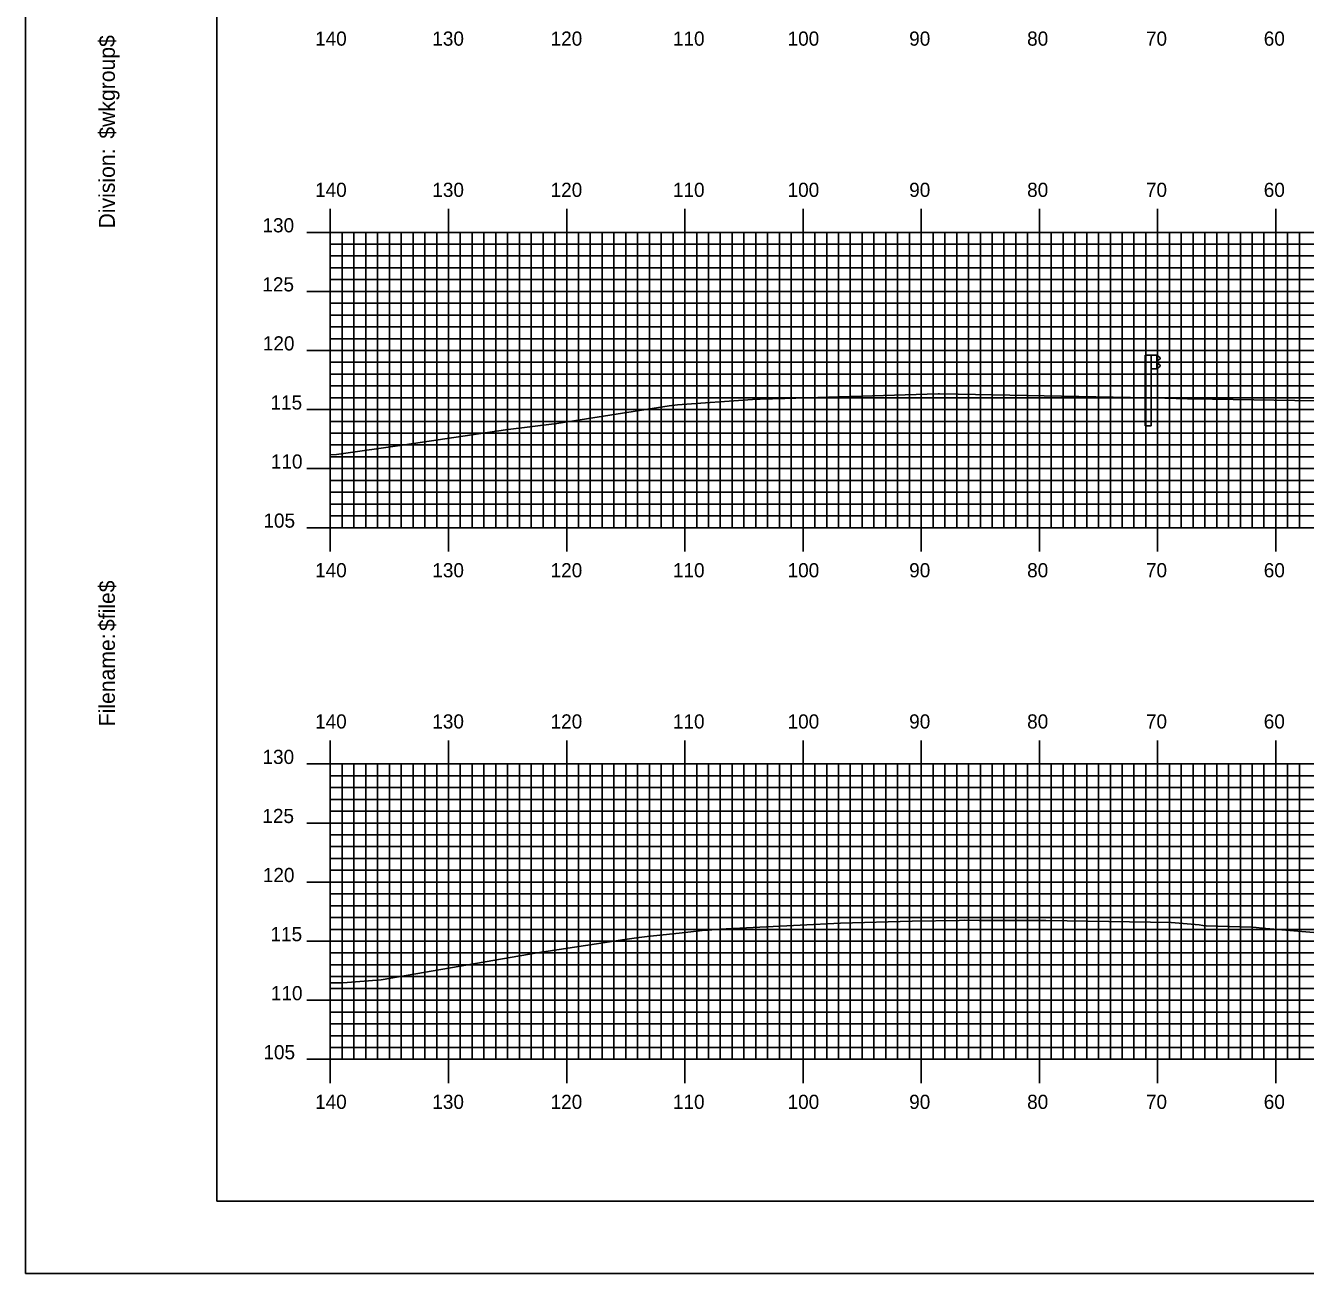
# Model space of a CAD drawing. Extents: x 1754314 to 1754654, y 442591 to 442811.
# Drawn here: x 1754314.2 to 1754422.5, y 442590.5 to 442696.2 of the extents above; entities that cross this region are included whole.
import ezdxf

# ---------------------------------------------------------------- set-up
doc = ezdxf.new("R2010")
doc.units = 0
for name, color, linetype in [('BORDER', 7, 'Continuous'), ('H_V ANNOTATION', 7, 'Continuous'), ('M_Guardrail', 7, 'Continuous'), ('M_Roadway_Centerline', 7, 'Continuous'), ('MAJOR', 7, 'Continuous'), ('MINOR', 7, 'Continuous'), ('PLOT BOUNDARY', 7, 'Continuous'), ('S_Roadway_Centerline', 7, 'Continuous')]:
    doc.layers.add(name, color=color, linetype=linetype)

msp = doc.modelspace()

# ---------------------------------------------------------------- linework, layer by layer
at = {"layer": 'BORDER'}
msp.add_lwpolyline([(1754330.4, 442596.67), (1754650.4, 442596.67), (1754650.4, 442806.67), (1754330.4, 442806.67)], close=True, dxfattribs=at)
at = {"layer": 'M_Guardrail'}
for p, q in [((1754408.96, 442668.28), (1754408.96, 442662.28)), ((1754409.45, 442668.28), (1754408.96, 442668.28)), ((1754409.94, 442668.28), (1754409.45, 442668.28)), ((1754409.45, 442668.28), (1754409.45, 442667.11)), ((1754409.94, 442667.11), (1754409.94, 442668.28)), ((1754409.94, 442668.21), (1754410.02, 442668.19)), ((1754409.95, 442667.74), (1754409.95, 442667.65)), ((1754410.18, 442667.94), (1754409.99, 442667.81)), ((1754409.99, 442667.59), (1754410.18, 442667.45)), ((1754410.04, 442668.19), (1754410.18, 442668.09)), ((1754409.45, 442662.28), (1754409.45, 442667.11)), ((1754409.45, 442667.11), (1754409.94, 442667.11)), ((1754410.02, 442667.2), (1754409.94, 442667.19)), ((1754410.18, 442667.31), (1754410.04, 442667.21)), ((1754409.45, 442662.28), (1754408.96, 442662.28))]:
    msp.add_line(p, q, dxfattribs=at)
for centre, major_axis, start_param, end_param in [((1754410.03, 442667.74), (-0.0789, 0), 5.323254, 6.283185), ((1754410.03, 442667.65), (-0.0789, 0), 6.283185, 7.243116), ((1754410.01, 442668.15), (0.0417, 0), 0.959931, 1.396263), ((1754410.13, 442668.01), (0.0877, 0), 5.323254, 7.243116), ((1754410.13, 442667.38), (0.0877, 0), 5.323254, 7.243116), ((1754410.01, 442667.24), (0.0417, 0), 4.886922, 5.323254)]:
    msp.add_ellipse(centre, major_axis=major_axis, ratio=0.995501, start_param=start_param, end_param=end_param, dxfattribs=at)
at = {"layer": 'MAJOR'}
for p, q in [((1754340, 442680.67), (1754340, 442678.67)), ((1754350, 442680.67), (1754350, 442678.67)), ((1754360, 442680.67), (1754360, 442678.67)), ((1754370, 442680.67), (1754370, 442678.67)), ((1754380, 442680.67), (1754380, 442678.67)), ((1754390, 442680.67), (1754390, 442678.67)), ((1754400, 442680.67), (1754400, 442678.67)), ((1754410, 442680.67), (1754410, 442678.67)), ((1754420, 442680.67), (1754420, 442678.67)), ((1754338, 442678.67), (1754340, 442678.67)), ((1754340, 442678.67), (1754620, 442678.67)), ((1754340, 442653.67), (1754340, 442678.67)), ((1754340, 442653.67), (1754340, 442678.67)), ((1754340, 442678.67), (1754620, 442678.67)), ((1754350, 442653.67), (1754350, 442678.67)), ((1754360, 442653.67), (1754360, 442678.67)), ((1754370, 442653.67), (1754370, 442678.67)), ((1754380, 442653.67), (1754380, 442678.67)), ((1754390, 442653.67), (1754390, 442678.67)), ((1754400, 442653.67), (1754400, 442678.67)), ((1754410, 442653.67), (1754410, 442678.67)), ((1754420, 442653.67), (1754420, 442678.67)), ((1754338, 442673.67), (1754340, 442673.67)), ((1754338, 442668.67), (1754340, 442668.67)), ((1754340, 442668.67), (1754620, 442668.67)), ((1754338, 442663.67), (1754340, 442663.67)), ((1754340, 442663.67), (1754620, 442663.67)), ((1754338, 442658.67), (1754340, 442658.67)), ((1754340, 442658.67), (1754620, 442658.67)), ((1754338, 442653.67), (1754340, 442653.67)), ((1754340, 442653.67), (1754620, 442653.67)), ((1754340, 442653.67), (1754620, 442653.67)), ((1754340, 442651.66), (1754340, 442653.67)), ((1754350, 442651.66), (1754350, 442653.67)), ((1754360, 442651.66), (1754360, 442653.67)), ((1754370, 442651.66), (1754370, 442653.67)), ((1754380, 442651.66), (1754380, 442653.67)), ((1754390, 442651.66), (1754390, 442653.67)), ((1754400, 442651.66), (1754400, 442653.67)), ((1754410, 442651.66), (1754410, 442653.67)), ((1754420, 442651.66), (1754420, 442653.67)), ((1754340, 442635.67), (1754340, 442633.67)), ((1754350, 442635.67), (1754350, 442633.67)), ((1754360, 442635.67), (1754360, 442633.67)), ((1754370, 442635.67), (1754370, 442633.67)), ((1754380, 442635.67), (1754380, 442633.67)), ((1754390, 442635.67), (1754390, 442633.67)), ((1754400, 442635.67), (1754400, 442633.67)), ((1754410, 442635.67), (1754410, 442633.67)), ((1754420, 442635.67), (1754420, 442633.67)), ((1754338, 442633.67), (1754340, 442633.67)), ((1754340, 442633.67), (1754620, 442633.67)), ((1754340, 442608.67), (1754340, 442633.67)), ((1754340, 442608.67), (1754340, 442633.67)), ((1754340, 442633.67), (1754620, 442633.67)), ((1754350, 442608.67), (1754350, 442633.67)), ((1754360, 442608.67), (1754360, 442633.67)), ((1754370, 442608.67), (1754370, 442633.67)), ((1754380, 442608.67), (1754380, 442633.67)), ((1754390, 442608.67), (1754390, 442633.67)), ((1754400, 442608.67), (1754400, 442633.67)), ((1754410, 442608.67), (1754410, 442633.67)), ((1754420, 442608.67), (1754420, 442633.67)), ((1754338, 442628.67), (1754340, 442628.67)), ((1754340, 442628.67), (1754620, 442628.67)), ((1754338, 442623.67), (1754340, 442623.67)), ((1754340, 442623.67), (1754620, 442623.67)), ((1754338, 442618.67), (1754340, 442618.67)), ((1754340, 442618.67), (1754620, 442618.67)), ((1754338, 442613.67), (1754340, 442613.67)), ((1754340, 442613.67), (1754620, 442613.67)), ((1754338, 442608.67), (1754340, 442608.67)), ((1754340, 442608.67), (1754620, 442608.67)), ((1754340, 442608.67), (1754620, 442608.67)), ((1754340, 442606.66), (1754340, 442608.67)), ((1754350, 442606.66), (1754350, 442608.67)), ((1754360, 442606.66), (1754360, 442608.67)), ((1754370, 442606.66), (1754370, 442608.67)), ((1754380, 442606.66), (1754380, 442608.67)), ((1754390, 442606.66), (1754390, 442608.67)), ((1754400, 442606.66), (1754400, 442608.67)), ((1754410, 442606.66), (1754410, 442608.67)), ((1754420, 442606.66), (1754420, 442608.67))]:
    msp.add_line(p, q, dxfattribs=at)
at = {"layer": 'MINOR'}
for p, q in [((1754341, 442653.67), (1754341, 442678.67)), ((1754342, 442653.67), (1754342, 442678.67)), ((1754343, 442653.67), (1754343, 442678.67)), ((1754344, 442653.67), (1754344, 442678.67)), ((1754345, 442653.67), (1754345, 442678.67)), ((1754346, 442653.67), (1754346, 442678.67)), ((1754347, 442653.67), (1754347, 442678.67)), ((1754348, 442653.67), (1754348, 442678.67)), ((1754349, 442653.67), (1754349, 442678.67)), ((1754351, 442653.67), (1754351, 442678.67)), ((1754352, 442653.67), (1754352, 442678.67)), ((1754353, 442653.67), (1754353, 442678.67)), ((1754354, 442653.67), (1754354, 442678.67)), ((1754355, 442653.67), (1754355, 442678.67)), ((1754356, 442653.67), (1754356, 442678.67)), ((1754357, 442653.67), (1754357, 442678.67)), ((1754358, 442653.67), (1754358, 442678.67)), ((1754359, 442653.67), (1754359, 442678.67)), ((1754361, 442653.67), (1754361, 442678.67)), ((1754362, 442653.67), (1754362, 442678.67)), ((1754363, 442653.67), (1754363, 442678.67)), ((1754364, 442653.67), (1754364, 442678.67)), ((1754365, 442653.67), (1754365, 442678.67)), ((1754366, 442653.67), (1754366, 442678.67)), ((1754367, 442653.67), (1754367, 442678.67)), ((1754368, 442653.67), (1754368, 442678.67)), ((1754369, 442653.67), (1754369, 442678.67)), ((1754371, 442653.67), (1754371, 442678.67)), ((1754372, 442653.67), (1754372, 442678.67)), ((1754373, 442653.67), (1754373, 442678.67)), ((1754374, 442653.67), (1754374, 442678.67)), ((1754375, 442653.67), (1754375, 442678.67)), ((1754376, 442653.67), (1754376, 442678.67)), ((1754377, 442653.67), (1754377, 442678.67)), ((1754378, 442653.67), (1754378, 442678.67)), ((1754379, 442653.67), (1754379, 442678.67)), ((1754381, 442653.67), (1754381, 442678.67)), ((1754382, 442653.67), (1754382, 442678.67)), ((1754383, 442653.67), (1754383, 442678.67)), ((1754384, 442653.67), (1754384, 442678.67)), ((1754385, 442653.67), (1754385, 442678.67)), ((1754386, 442653.67), (1754386, 442678.67)), ((1754387, 442653.67), (1754387, 442678.67)), ((1754388, 442653.67), (1754388, 442678.67)), ((1754389, 442653.67), (1754389, 442678.67)), ((1754391, 442653.67), (1754391, 442678.67)), ((1754392, 442653.67), (1754392, 442678.67)), ((1754393, 442653.67), (1754393, 442678.67)), ((1754394, 442653.67), (1754394, 442678.67)), ((1754395, 442653.67), (1754395, 442678.67)), ((1754396, 442653.67), (1754396, 442678.67)), ((1754397, 442653.67), (1754397, 442678.67)), ((1754398, 442653.67), (1754398, 442678.67)), ((1754399, 442653.67), (1754399, 442678.67)), ((1754401, 442653.67), (1754401, 442678.67)), ((1754402, 442653.67), (1754402, 442678.67)), ((1754403, 442653.67), (1754403, 442678.67)), ((1754404, 442653.67), (1754404, 442678.67)), ((1754405, 442653.67), (1754405, 442678.67)), ((1754406, 442653.67), (1754406, 442678.67)), ((1754407, 442653.67), (1754407, 442678.67)), ((1754408, 442653.67), (1754408, 442678.67)), ((1754409, 442653.67), (1754409, 442678.67)), ((1754411, 442653.67), (1754411, 442678.67)), ((1754412, 442653.67), (1754412, 442678.67)), ((1754413, 442653.67), (1754413, 442678.67)), ((1754414, 442653.67), (1754414, 442678.67)), ((1754415, 442653.67), (1754415, 442678.67)), ((1754416, 442653.67), (1754416, 442678.67)), ((1754417, 442653.67), (1754417, 442678.67)), ((1754418, 442653.67), (1754418, 442678.67)), ((1754419, 442653.67), (1754419, 442678.67)), ((1754421, 442653.67), (1754421, 442678.67)), ((1754422, 442653.67), (1754422, 442678.67)), ((1754340, 442677.67), (1754620, 442677.67)), ((1754340, 442677.67), (1754342.01, 442677.67)), ((1754340, 442676.67), (1754620, 442676.67)), ((1754340, 442676.67), (1754342.01, 442676.67)), ((1754340, 442675.67), (1754620, 442675.67)), ((1754340, 442675.67), (1754342.01, 442675.67)), ((1754340, 442674.67), (1754620, 442674.67)), ((1754340, 442674.67), (1754342.01, 442674.67)), ((1754340, 442673.67), (1754620, 442673.67)), ((1754340, 442672.67), (1754620, 442672.67)), ((1754340, 442672.67), (1754342.01, 442672.67)), ((1754340, 442671.67), (1754620, 442671.67)), ((1754340, 442671.67), (1754342.01, 442671.67)), ((1754340, 442670.67), (1754620, 442670.67)), ((1754340, 442670.67), (1754342.01, 442670.67)), ((1754340, 442669.67), (1754620, 442669.67)), ((1754340, 442669.67), (1754342.01, 442669.67)), ((1754340, 442667.67), (1754620, 442667.67)), ((1754340, 442667.67), (1754342.01, 442667.67)), ((1754340, 442666.67), (1754620, 442666.67)), ((1754340, 442666.67), (1754342.01, 442666.67)), ((1754340, 442665.67), (1754620, 442665.67)), ((1754340, 442665.67), (1754342.01, 442665.67)), ((1754340, 442664.67), (1754620, 442664.67)), ((1754340, 442664.67), (1754342.01, 442664.67)), ((1754340, 442662.67), (1754620, 442662.67)), ((1754340, 442662.67), (1754342.01, 442662.67)), ((1754340, 442661.67), (1754620, 442661.67)), ((1754340, 442661.67), (1754342.01, 442661.67)), ((1754340, 442660.67), (1754620, 442660.67)), ((1754340, 442660.67), (1754342.01, 442660.67)), ((1754340, 442659.67), (1754620, 442659.67)), ((1754340, 442659.67), (1754342.01, 442659.67)), ((1754340, 442657.67), (1754620, 442657.67)), ((1754340, 442657.67), (1754342.01, 442657.67)), ((1754340, 442656.67), (1754620, 442656.67)), ((1754340, 442656.67), (1754342.01, 442656.67)), ((1754340, 442655.67), (1754620, 442655.67)), ((1754340, 442655.67), (1754342.01, 442655.67)), ((1754340, 442654.67), (1754620, 442654.67)), ((1754340, 442654.67), (1754342.01, 442654.67)), ((1754341, 442608.67), (1754341, 442633.67)), ((1754342, 442608.67), (1754342, 442633.67)), ((1754343, 442608.67), (1754343, 442633.67)), ((1754344, 442608.67), (1754344, 442633.67)), ((1754345, 442608.67), (1754345, 442633.67)), ((1754346, 442608.67), (1754346, 442633.67)), ((1754347, 442608.67), (1754347, 442633.67)), ((1754348, 442608.67), (1754348, 442633.67)), ((1754349, 442608.67), (1754349, 442633.67)), ((1754351, 442608.67), (1754351, 442633.67)), ((1754352, 442608.67), (1754352, 442633.67)), ((1754353, 442608.67), (1754353, 442633.67)), ((1754354, 442608.67), (1754354, 442633.67)), ((1754355, 442608.67), (1754355, 442633.67)), ((1754356, 442608.67), (1754356, 442633.67)), ((1754357, 442608.67), (1754357, 442633.67)), ((1754358, 442608.67), (1754358, 442633.67)), ((1754359, 442608.67), (1754359, 442633.67)), ((1754361, 442608.67), (1754361, 442633.67)), ((1754362, 442608.67), (1754362, 442633.67)), ((1754363, 442608.67), (1754363, 442633.67)), ((1754364, 442608.67), (1754364, 442633.67)), ((1754365, 442608.67), (1754365, 442633.67)), ((1754366, 442608.67), (1754366, 442633.67)), ((1754367, 442608.67), (1754367, 442633.67)), ((1754368, 442608.67), (1754368, 442633.67)), ((1754369, 442608.67), (1754369, 442633.67)), ((1754371, 442608.67), (1754371, 442633.67)), ((1754372, 442608.67), (1754372, 442633.67)), ((1754373, 442608.67), (1754373, 442633.67)), ((1754374, 442608.67), (1754374, 442633.67)), ((1754375, 442608.67), (1754375, 442633.67)), ((1754376, 442608.67), (1754376, 442633.67)), ((1754377, 442608.67), (1754377, 442633.67)), ((1754378, 442608.67), (1754378, 442633.67)), ((1754379, 442608.67), (1754379, 442633.67)), ((1754381, 442608.67), (1754381, 442633.67)), ((1754382, 442608.67), (1754382, 442633.67)), ((1754383, 442608.67), (1754383, 442633.67)), ((1754384, 442608.67), (1754384, 442633.67)), ((1754385, 442608.67), (1754385, 442633.67)), ((1754386, 442608.67), (1754386, 442633.67)), ((1754387, 442608.67), (1754387, 442633.67)), ((1754388, 442608.67), (1754388, 442633.67)), ((1754389, 442608.67), (1754389, 442633.67)), ((1754391, 442608.67), (1754391, 442633.67)), ((1754392, 442608.67), (1754392, 442633.67)), ((1754393, 442608.67), (1754393, 442633.67)), ((1754394, 442608.67), (1754394, 442633.67)), ((1754395, 442608.67), (1754395, 442633.67)), ((1754396, 442608.67), (1754396, 442633.67)), ((1754397, 442608.67), (1754397, 442633.67)), ((1754398, 442608.67), (1754398, 442633.67)), ((1754399, 442608.67), (1754399, 442633.67)), ((1754401, 442608.67), (1754401, 442633.67)), ((1754402, 442608.67), (1754402, 442633.67)), ((1754403, 442608.67), (1754403, 442633.67)), ((1754404, 442608.67), (1754404, 442633.67)), ((1754405, 442608.67), (1754405, 442633.67)), ((1754406, 442608.67), (1754406, 442633.67)), ((1754407, 442608.67), (1754407, 442633.67)), ((1754408, 442608.67), (1754408, 442633.67)), ((1754409, 442608.67), (1754409, 442633.67)), ((1754411, 442608.67), (1754411, 442633.67)), ((1754412, 442608.67), (1754412, 442633.67)), ((1754413, 442608.67), (1754413, 442633.67)), ((1754414, 442608.67), (1754414, 442633.67)), ((1754415, 442608.67), (1754415, 442633.67)), ((1754416, 442608.67), (1754416, 442633.67)), ((1754417, 442608.67), (1754417, 442633.67)), ((1754418, 442608.67), (1754418, 442633.67)), ((1754419, 442608.67), (1754419, 442633.67)), ((1754421, 442608.67), (1754421, 442633.67)), ((1754422, 442608.67), (1754422, 442633.67)), ((1754340, 442632.67), (1754620, 442632.67)), ((1754340, 442632.67), (1754342.01, 442632.67)), ((1754340, 442631.67), (1754620, 442631.67)), ((1754340, 442631.67), (1754342.01, 442631.67)), ((1754340, 442630.67), (1754620, 442630.67)), ((1754340, 442630.67), (1754342.01, 442630.67)), ((1754340, 442629.67), (1754620, 442629.67)), ((1754340, 442629.67), (1754342.01, 442629.67)), ((1754340, 442627.67), (1754620, 442627.67)), ((1754340, 442627.67), (1754342.01, 442627.67)), ((1754340, 442626.67), (1754620, 442626.67)), ((1754340, 442626.67), (1754342.01, 442626.67)), ((1754340, 442625.67), (1754620, 442625.67)), ((1754340, 442625.67), (1754342.01, 442625.67)), ((1754340, 442624.67), (1754620, 442624.67)), ((1754340, 442624.67), (1754342.01, 442624.67)), ((1754340, 442622.67), (1754620, 442622.67)), ((1754340, 442622.67), (1754342.01, 442622.67)), ((1754340, 442621.67), (1754620, 442621.67)), ((1754340, 442621.67), (1754342.01, 442621.67)), ((1754340, 442620.67), (1754620, 442620.67)), ((1754340, 442620.67), (1754342.01, 442620.67)), ((1754340, 442619.67), (1754620, 442619.67)), ((1754340, 442619.67), (1754342.01, 442619.67)), ((1754340, 442617.67), (1754620, 442617.67)), ((1754340, 442617.67), (1754342.01, 442617.67)), ((1754340, 442616.67), (1754620, 442616.67)), ((1754340, 442616.67), (1754342.01, 442616.67)), ((1754340, 442615.67), (1754620, 442615.67)), ((1754340, 442615.67), (1754342.01, 442615.67)), ((1754340, 442614.67), (1754620, 442614.67)), ((1754340, 442614.67), (1754342.01, 442614.67)), ((1754340, 442612.67), (1754620, 442612.67)), ((1754340, 442612.67), (1754342.01, 442612.67)), ((1754340, 442611.67), (1754620, 442611.67)), ((1754340, 442611.67), (1754342.01, 442611.67)), ((1754340, 442610.67), (1754620, 442610.67)), ((1754340, 442610.67), (1754342.01, 442610.67)), ((1754340, 442609.67), (1754620, 442609.67)), ((1754340, 442609.67), (1754342.01, 442609.67))]:
    msp.add_line(p, q, dxfattribs=at)
at = {"layer": 'PLOT BOUNDARY'}
msp.add_lwpolyline([(1754314.22, 442590.55), (1754654.22, 442590.55), (1754654.22, 442810.55), (1754314.22, 442810.55)], close=True, dxfattribs=at)
at = {"layer": 'S_Roadway_Centerline'}
for points in [[(1754340, 442659.85), (1754340.52, 442659.86), (1754346.29, 442660.69), (1754354.81, 442661.94), (1754359.16, 442662.5), (1754368.67, 442663.99), (1754369.39, 442664.08), (1754375.71, 442664.52), (1754376.36, 442664.56), (1754378.45, 442664.62), (1754391.42, 442665.01), (1754391.45, 442665.01), (1754391.46, 442665.01), (1754391.54, 442665.01), (1754393.12, 442664.98), (1754410.6, 442664.64), (1754412.52, 442664.59), (1754414.64, 442664.54), (1754423.35, 442664.42)], [(1754340, 442615.15), (1754341.07, 442615.15), (1754344.3, 442615.39), (1754357.5, 442617.68), (1754362.52, 442618.44), (1754364.71, 442618.79), (1754365.13, 442618.85), (1754365.92, 442618.96), (1754366.82, 442619.06), (1754369.52, 442619.34), (1754371.72, 442619.6), (1754371.84, 442619.61), (1754371.95, 442619.6), (1754372.93, 442619.7), (1754383.17, 442620.2), (1754389.24, 442620.36), (1754393.22, 442620.42), (1754393.67, 442620.44), (1754394.9, 442620.43), (1754400.54, 442620.43), (1754402.35, 442620.39), (1754411.15, 442620.24), (1754413.19, 442620.07), (1754413.52, 442620.04), (1754413.82, 442620.01), (1754414.12, 442619.98), (1754418.07, 442619.85), (1754419.15, 442619.74), (1754424.23, 442619.32)]]:
    msp.add_lwpolyline(points, dxfattribs=at)

# ---------------------------------------------------------------- texts
at = {"layer": 'BORDER'}
for s, p in [('$wkgroup$', (1754321.77, 442686.6)), ('$wkgroup$', (1754321.77, 442686.6)), ('Division:', (1754321.77, 442679)), ('Division:', (1754321.77, 442679)), ('$file$', (1754321.77, 442644.92)), ('$file$', (1754321.77, 442644.92)), ('Filename:', (1754321.77, 442636.86)), ('Filename:', (1754321.77, 442636.86))]:
    msp.add_text(s, height=1.339, rotation=90, dxfattribs=at).set_placement(p)
at = {"layer": 'H_V ANNOTATION'}
for s, p in [('140', (1754338.71, 442694.47)), ('130', (1754348.63, 442694.47)), ('120', (1754358.64, 442694.47)), ('110', (1754368.99, 442694.47)), ('100', (1754378.69, 442694.47)), ('90', (1754388.98, 442694.47)), ('80', (1754398.96, 442694.47)), ('70', (1754409.01, 442694.47)), ('60', (1754418.98, 442694.47)), ('140', (1754338.71, 442681.67)), ('130', (1754348.63, 442681.67)), ('120', (1754358.64, 442681.67)), ('110', (1754368.99, 442681.67)), ('100', (1754378.69, 442681.67)), ('90', (1754388.98, 442681.67)), ('80', (1754398.96, 442681.67)), ('70', (1754409.01, 442681.67)), ('60', (1754418.98, 442681.67)), ('130', (1754334.26, 442678.67)), ('125', (1754334.25, 442673.67)), ('120', (1754334.29, 442668.67)), ('115', (1754334.94, 442663.67)), ('110', (1754334.97, 442658.67)), ('105', (1754334.34, 442653.67)), ('140', (1754338.71, 442649.47)), ('130', (1754348.63, 442649.47)), ('120', (1754358.64, 442649.47)), ('110', (1754368.99, 442649.47)), ('100', (1754378.69, 442649.47)), ('90', (1754388.98, 442649.47)), ('80', (1754398.96, 442649.47)), ('70', (1754409.01, 442649.47)), ('60', (1754418.98, 442649.47)), ('140', (1754338.71, 442636.67)), ('130', (1754348.63, 442636.67)), ('120', (1754358.64, 442636.67)), ('110', (1754368.99, 442636.67)), ('100', (1754378.69, 442636.67)), ('90', (1754388.98, 442636.67)), ('80', (1754398.96, 442636.67)), ('70', (1754409.01, 442636.67)), ('60', (1754418.98, 442636.67)), ('130', (1754334.26, 442633.67)), ('125', (1754334.25, 442628.67)), ('120', (1754334.29, 442623.67)), ('115', (1754334.94, 442618.67)), ('110', (1754334.97, 442613.67)), ('105', (1754334.34, 442608.67)), ('140', (1754338.71, 442604.47)), ('130', (1754348.63, 442604.47)), ('120', (1754358.64, 442604.47)), ('110', (1754368.99, 442604.47)), ('100', (1754378.69, 442604.47)), ('90', (1754388.98, 442604.47)), ('80', (1754398.96, 442604.47)), ('70', (1754409.01, 442604.47)), ('60', (1754418.98, 442604.47))]:
    msp.add_text(s, height=1.2, dxfattribs=at).set_placement(p)
at = {"layer": 'M_Roadway_Centerline'}
for s, p in [('L', (1754391.44, 442665)), ('C', (1754391.44, 442665.01)), ('C', (1754393.66, 442620.44)), ('L', (1754393.66, 442620.43))]:
    msp.add_text(s, height=0.0146, dxfattribs=at).set_placement(p)
at = {"layer": 'MAJOR'}
for p in [(1754340, 442653.67), (1754340, 442608.67)]:
    msp.add_text('-', height=0.012, dxfattribs=at).set_placement(p)

doc.saveas('drawing.dxf')
